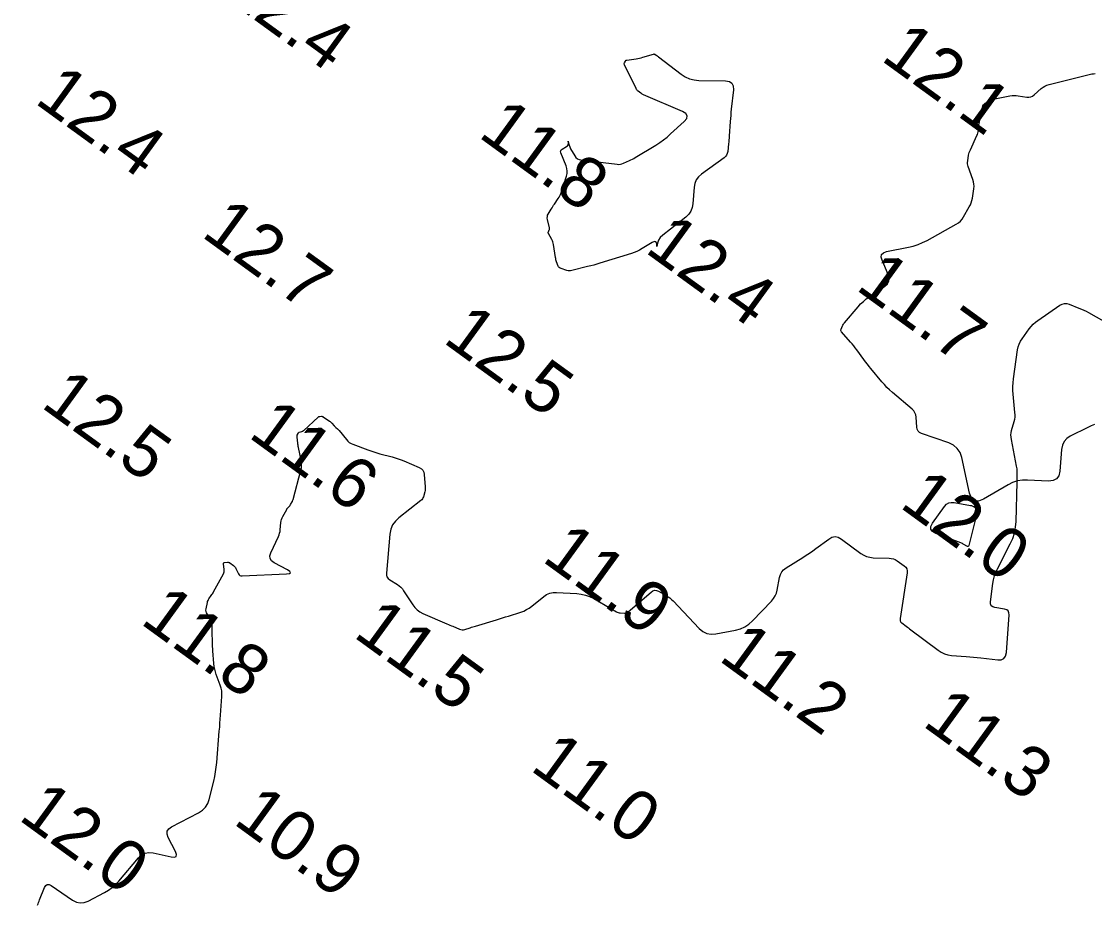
# Model space of a CAD drawing. Extents: x 815352 to 820877, y 582403 to 597439.
# Drawn here: x 818975.7 to 819081.8, y 587258.8 to 587346.1 of the extents above; entities that cross this region are included whole.
import ezdxf

# ---------------------------------------------------------------- set-up
doc = ezdxf.new("R2010")
doc.units = 0
doc.layers.add('V-CONT-EL12', color=7, linetype='Continuous')
doc.layers.add('V-TOPO-SOUN', color=7, linetype='Continuous')

msp = doc.modelspace()

# ---------------------------------------------------------------- linework, layer by layer
at = {"layer": 'V-CONT-EL12'}
for points in [[(819029.98, 587321.41), (819029.85, 587321.41), (819029.73, 587321.42), (819029.6, 587321.45), (819029.04, 587321.62), (819028.94, 587321.66), (819028.86, 587321.72), (819028.8, 587321.79), (819028.75, 587321.88), (819028.6, 587322.29), (819028.57, 587322.4), (819028.54, 587322.5), (819028.52, 587322.61), (819028.5, 587322.72), (819028.3, 587324.02), (819028.28, 587324.14), (819028.24, 587324.27), (819028.19, 587324.38), (819028.13, 587324.5), (819027.8, 587325.08), (819027.78, 587325.13), (819027.77, 587325.18), (819027.78, 587325.22), (819027.79, 587325.27), (819027.88, 587325.46), (819027.9, 587325.5), (819027.91, 587325.55), (819027.91, 587325.6), (819027.91, 587325.65), (819027.7, 587326.48), (819027.68, 587326.62), (819027.69, 587326.76), (819027.72, 587326.89), (819027.78, 587327.01), (819028.08, 587327.51), (819028.15, 587327.63), (819028.23, 587327.76), (819028.31, 587327.88), (819028.39, 587328), (819028.76, 587328.54), (819028.85, 587328.68), (819028.92, 587328.82), (819028.98, 587328.96), (819029.04, 587329.11), (819029.58, 587330.75), (819029.65, 587331.01), (819029.66, 587331.27), (819029.63, 587331.52), (819029.55, 587331.78), (819029.03, 587333.08), (819029, 587333.19), (819029.01, 587333.28), (819029.06, 587333.37), (819029.15, 587333.44), (819029.58, 587333.69), (819029.67, 587333.76), (819029.73, 587333.85), (819029.77, 587333.95), (819029.77, 587334.07), (819029.76, 587334.23), (819029.79, 587334.03), (819029.83, 587333.83), (819029.9, 587333.65), (819029.99, 587333.47), (819030.4, 587332.77), (819030.52, 587332.61), (819030.66, 587332.49), (819030.82, 587332.41), (819031.01, 587332.37), (819034.59, 587331.94), (819034.75, 587331.93), (819034.91, 587331.94), (819035.06, 587331.97), (819035.21, 587332.03), (819035.8, 587332.3), (819035.95, 587332.36), (819036.09, 587332.44), (819036.23, 587332.51), (819036.37, 587332.6), (819038.42, 587333.84), (819038.8, 587334.08), (819039.17, 587334.35), (819039.53, 587334.63), (819039.87, 587334.93), (819041.22, 587336.18), (819041.46, 587336.47), (819041.51, 587336.73), (819041.37, 587336.96), (819041.05, 587337.16), (819037.2, 587338.81), (819037.13, 587338.84), (819037.06, 587338.88), (819036.99, 587338.92), (819036.93, 587338.97), (819036.67, 587339.16), (819036.61, 587339.21), (819036.55, 587339.27), (819036.51, 587339.34), (819036.47, 587339.41), (819035.31, 587341.78), (819035.29, 587341.82), (819035.29, 587341.87), (819035.29, 587341.91), (819035.31, 587341.96), (819035.4, 587342.14), (819035.43, 587342.18), (819035.46, 587342.21), (819035.5, 587342.23), (819035.54, 587342.24), (819036.45, 587342.37), (819036.62, 587342.4), (819036.78, 587342.43), (819036.95, 587342.47), (819037.11, 587342.52), (819038.17, 587342.83), (819038.22, 587342.84), (819038.26, 587342.83), (819038.31, 587342.82), (819038.35, 587342.8), (819038.51, 587342.68), (819038.55, 587342.65), (819038.59, 587342.62), (819038.63, 587342.59), (819038.67, 587342.56), (819040.92, 587340.84), (819041.32, 587340.58), (819041.74, 587340.39), (819042.19, 587340.27), (819042.67, 587340.23), (819045.31, 587340.17), (819045.68, 587340.11), (819045.93, 587339.94), (819046.06, 587339.68), (819046.07, 587339.31), (819045.86, 587337.38), (819045.83, 587337.07), (819045.81, 587336.77), (819045.78, 587336.47), (819045.76, 587336.16), (819045.66, 587334.73), (819045.64, 587334.53), (819045.63, 587334.34), (819045.61, 587334.15), (819045.59, 587333.95), (819045.51, 587333.19), (819045.47, 587333), (819045.4, 587332.84), (819045.3, 587332.7), (819045.16, 587332.57), (819042.91, 587330.95), (819042.62, 587330.69), (819042.4, 587330.39), (819042.26, 587330.04), (819042.19, 587329.66), (819042.08, 587328.03), (819042.01, 587327.65), (819041.87, 587327.3), (819041.66, 587326.99), (819041.38, 587326.72), (819039.09, 587324.93), (819038.85, 587324.7), (819038.68, 587324.43), (819038.56, 587324.14), (819038.51, 587323.81), (819038.51, 587323.92), (819038.5, 587324.15), (819038.42, 587324.28), (819038.27, 587324.29), (819038.05, 587324.2), (819037.05, 587323.6), (819036.79, 587323.46), (819036.53, 587323.33), (819036.26, 587323.22), (819035.99, 587323.13), (819032.88, 587322.16), (819032.58, 587322.07), (819032.28, 587321.98), (819031.98, 587321.9), (819031.67, 587321.82), (819030.11, 587321.44)], [(819068.77, 587294.4), (819068.7, 587294.44), (819068.62, 587294.48), (819068.54, 587294.51), (819066.07, 587295.45), (819065.74, 587295.63), (819065.58, 587295.86), (819065.59, 587296.14), (819065.76, 587296.47), (819066.94, 587298.12), (819067.13, 587298.33), (819067.35, 587298.46), (819067.6, 587298.52), (819067.89, 587298.51), (819069.52, 587298.22), (819069.6, 587298.2), (819069.67, 587298.17), (819069.75, 587298.14), (819069.82, 587298.1), (819070.1, 587297.92), (819070.16, 587297.87), (819070.19, 587297.81), (819070.21, 587297.74), (819070.2, 587297.67), (819069.33, 587294.26), (819069.3, 587294.19), (819069.26, 587294.15), (819069.21, 587294.15), (819069.14, 587294.18), (819068.85, 587294.36)]]:
    msp.add_lwpolyline(points, close=True, dxfattribs=at)
for points in [[(819081.76, 587306.22), (819081.42, 587306.08), (819081.09, 587305.92), (819079.36, 587305.05), (819079.01, 587304.82), (819078.75, 587304.53), (819078.58, 587304.18), (819078.5, 587303.76), (819078.32, 587301.6), (819078.22, 587301.16), (819078.01, 587300.85), (819077.67, 587300.67), (819077.22, 587300.63), (819075.14, 587300.73), (819074.64, 587300.72), (819074.15, 587300.64), (819073.67, 587300.48), (819073.22, 587300.26), (819070.79, 587298.84), (819070.29, 587298.63), (819069.89, 587298.67), (819069.59, 587298.94), (819069.41, 587299.44), (819068.64, 587302.95), (819068.47, 587303.44), (819068.2, 587303.85), (819067.83, 587304.17), (819067.35, 587304.39), (819064.67, 587305.33), (819064.47, 587305.43), (819064.33, 587305.57), (819064.23, 587305.75), (819064.19, 587305.97), (819064.13, 587306.93), (819064.09, 587307.16), (819064.02, 587307.37), (819063.9, 587307.56), (819063.73, 587307.72), (819061.79, 587309.38), (819061.51, 587309.63), (819061.24, 587309.89), (819060.99, 587310.16), (819060.74, 587310.45), (819059.67, 587311.74), (819059.49, 587311.96), (819059.32, 587312.18), (819059.14, 587312.41), (819058.97, 587312.63), (819058.27, 587313.6), (819058.12, 587313.8), (819057.96, 587313.99), (819057.8, 587314.19), (819057.64, 587314.37), (819056.77, 587315.36), (819056.72, 587315.43), (819056.7, 587315.5), (819056.7, 587315.58), (819056.72, 587315.65), (819056.86, 587315.97), (819056.9, 587316.05), (819056.95, 587316.13), (819056.99, 587316.2), (819057.05, 587316.27), (819058.4, 587317.86), (819058.65, 587318.13), (819058.92, 587318.39), (819059.21, 587318.63), (819059.51, 587318.85), (819061.05, 587319.9), (819061.3, 587320.13), (819061.45, 587320.4), (819061.47, 587320.7), (819061.37, 587321.03), (819060.76, 587322.45), (819060.68, 587322.76), (819060.72, 587323.01), (819060.9, 587323.19), (819061.21, 587323.3), (819063.37, 587323.73), (819063.85, 587323.85), (819064.32, 587324), (819064.77, 587324.19), (819065.21, 587324.41), (819068.09, 587326.01), (819068.31, 587326.15), (819068.51, 587326.32), (819068.68, 587326.52), (819068.82, 587326.73), (819069.38, 587327.72), (819069.49, 587327.93), (819069.58, 587328.14), (819069.64, 587328.37), (819069.69, 587328.59), (819069.84, 587329.52), (819069.86, 587329.76), (819069.85, 587329.98), (819069.81, 587330.21), (819069.75, 587330.43), (819069.28, 587331.71), (819069.24, 587331.85), (819069.22, 587331.98), (819069.22, 587332.12), (819069.23, 587332.26), (819069.32, 587332.83), (819069.35, 587332.97), (819069.38, 587333.1), (819069.43, 587333.24), (819069.49, 587333.37), (819070.14, 587334.78), (819070.19, 587334.89), (819070.23, 587335.02), (819070.26, 587335.14), (819070.28, 587335.27), (819070.34, 587335.88), (819070.35, 587335.96), (819070.37, 587336.04), (819070.38, 587336.12), (819070.4, 587336.19), (819070.49, 587336.5), (819070.51, 587336.58), (819070.53, 587336.66), (819070.55, 587336.73), (819070.56, 587336.81), (819070.69, 587337.58), (819070.72, 587337.7), (819070.78, 587337.8), (819070.86, 587337.89), (819070.96, 587337.96), (819071.42, 587338.22), (819071.54, 587338.28), (819071.66, 587338.32), (819071.78, 587338.36), (819071.91, 587338.39), (819073.4, 587338.69), (819073.61, 587338.72), (819073.82, 587338.73), (819074.02, 587338.73), (819074.23, 587338.71), (819075.07, 587338.57), (819075.27, 587338.56), (819075.46, 587338.6), (819075.64, 587338.67), (819075.8, 587338.79), (819076.49, 587339.42), (819076.67, 587339.56), (819076.86, 587339.67), (819077.06, 587339.76), (819077.27, 587339.83), (819081.48, 587340.86), (819081.65, 587340.89), (819081.82, 587340.91)], [(818977.3, 587258.72), (818977.36, 587258.84), (818977.41, 587258.97), (818977.47, 587259.1), (818977.52, 587259.23), (818978.01, 587260.45), (818978.13, 587260.65), (818978.27, 587260.75), (818978.45, 587260.75), (818978.65, 587260.65), (818980.77, 587259.21), (818981.15, 587259.01), (818981.53, 587258.93), (818981.93, 587258.97), (818982.32, 587259.12), (818983.94, 587259.97), (818984.32, 587260.2), (818984.69, 587260.46), (818985.02, 587260.75), (818985.33, 587261.08), (818987.29, 587263.4), (818987.59, 587263.68), (818987.93, 587263.85), (818988.31, 587263.92), (818988.72, 587263.88), (818990.53, 587263.48), (818990.85, 587263.45), (818991.02, 587263.53), (818991.05, 587263.71), (818990.94, 587264.01), (818990.22, 587265.4), (818990.11, 587265.73), (818990.12, 587266.02), (818990.27, 587266.26), (818990.56, 587266.46), (818993.23, 587267.84), (818993.61, 587268.09), (818993.91, 587268.39), (818994.13, 587268.75), (818994.28, 587269.17), (818994.72, 587270.98), (818994.82, 587271.43), (818994.9, 587271.89), (818994.97, 587272.34), (818995.02, 587272.81), (818995.27, 587275.9), (818995.31, 587276.3), (818995.34, 587276.7), (818995.37, 587277.1), (818995.4, 587277.5), (818995.53, 587279.34), (818995.53, 587279.63), (818995.51, 587279.9), (818995.46, 587280.17), (818995.37, 587280.44), (818994.97, 587281.51), (818994.89, 587281.78), (818994.82, 587282.04), (818994.77, 587282.31), (818994.73, 587282.59), (818994.63, 587283.85), (818994.62, 587284.05), (818994.61, 587284.26), (818994.6, 587284.46), (818994.59, 587284.67), (818994.56, 587285.71), (818994.56, 587285.8), (818994.56, 587285.9), (818994.56, 587285.99), (818994.56, 587286.09), (818994.58, 587286.47), (818994.57, 587286.56), (818994.55, 587286.65), (818994.52, 587286.73), (818994.48, 587286.82), (818994.06, 587287.49), (818994, 587287.61), (818993.96, 587287.74), (818993.95, 587287.87), (818993.97, 587288.01), (818994.1, 587288.64), (818994.12, 587288.73), (818994.16, 587288.83), (818994.2, 587288.91), (818994.25, 587289), (818994.48, 587289.33), (818994.54, 587289.41), (818994.6, 587289.49), (818994.65, 587289.58), (818994.7, 587289.67), (818995.68, 587291.46), (818995.72, 587291.57), (818995.75, 587291.67), (818995.76, 587291.78), (818995.76, 587291.89), (818995.69, 587292.44), (818995.69, 587292.5), (818995.71, 587292.54), (818995.75, 587292.57), (818995.8, 587292.58), (818996.08, 587292.6), (818996.14, 587292.6), (818996.21, 587292.59), (818996.27, 587292.57), (818996.32, 587292.53), (818996.68, 587292.28), (818996.75, 587292.22), (818996.81, 587292.16), (818996.87, 587292.08), (818996.91, 587292), (818997.16, 587291.47), (818997.23, 587291.37), (818997.31, 587291.3), (818997.41, 587291.26), (818997.53, 587291.25), (819001.91, 587291.46), (819002.2, 587291.49), (819002.3, 587291.57), (819002.24, 587291.68), (819002, 587291.84), (819000.68, 587292.55), (819000.43, 587292.74), (819000.29, 587292.97), (819000.27, 587293.23), (819000.36, 587293.53), (819001.11, 587295.15), (819001.18, 587295.31), (819001.23, 587295.47), (819001.27, 587295.64), (819001.29, 587295.81), (819001.36, 587296.54), (819001.38, 587296.69), (819001.42, 587296.84), (819001.47, 587296.98), (819001.54, 587297.11), (819001.94, 587297.83), (819001.96, 587297.87), (819001.99, 587297.91), (819002.02, 587297.95), (819002.06, 587297.99), (819002.2, 587298.14), (819002.23, 587298.18), (819002.26, 587298.22), (819002.29, 587298.26), (819002.32, 587298.3), (819002.46, 587298.56), (819002.49, 587298.61), (819002.52, 587298.67), (819002.54, 587298.73), (819002.56, 587298.8), (819003.34, 587301.7), (819003.39, 587301.95), (819003.41, 587302.19), (819003.4, 587302.44), (819003.36, 587302.68), (819003.09, 587303.94), (819003.07, 587304.05), (819003.05, 587304.16), (819003.03, 587304.27), (819003.02, 587304.38), (819002.96, 587304.95), (819002.96, 587305), (819002.96, 587305.05), (819002.97, 587305.1), (819002.98, 587305.15), (819003.05, 587305.33), (819003.07, 587305.38), (819003.1, 587305.41), (819003.14, 587305.44), (819003.18, 587305.46), (819003.43, 587305.53), (819003.49, 587305.55), (819003.54, 587305.57), (819003.59, 587305.61), (819003.63, 587305.64), (819005.04, 587306.95), (819005.07, 587306.98), (819005.11, 587307), (819005.15, 587307.01), (819005.19, 587307.02), (819005.37, 587307.03), (819005.41, 587307.03), (819005.45, 587307.02), (819005.49, 587307.01), (819005.53, 587306.99), (819006.16, 587306.56), (819006.23, 587306.51), (819006.28, 587306.46), (819006.34, 587306.41), (819006.39, 587306.35), (819006.62, 587306.1), (819006.65, 587306.05), (819006.7, 587306.01), (819006.74, 587305.97), (819006.78, 587305.93), (819006.96, 587305.78), (819007, 587305.74), (819007.04, 587305.7), (819007.08, 587305.65), (819007.12, 587305.61), (819007.83, 587304.73), (819007.96, 587304.58), (819008.12, 587304.45), (819008.29, 587304.34), (819008.48, 587304.26), (819009.95, 587303.7), (819010.24, 587303.6), (819010.54, 587303.5), (819010.84, 587303.41), (819011.14, 587303.32), (819012.35, 587303.01), (819012.65, 587302.92), (819012.94, 587302.83), (819013.24, 587302.72), (819013.52, 587302.61), (819015.03, 587301.97), (819015.24, 587301.85), (819015.39, 587301.7), (819015.48, 587301.51), (819015.53, 587301.28), (819015.62, 587300.05), (819015.63, 587299.92), (819015.62, 587299.8), (819015.6, 587299.68), (819015.57, 587299.56), (819015.45, 587299.08), (819015.4, 587298.97), (819015.35, 587298.86), (819015.27, 587298.77), (819015.18, 587298.69), (819013.02, 587296.99), (819012.67, 587296.66), (819012.4, 587296.29), (819012.23, 587295.86), (819012.14, 587295.39), (819011.78, 587291.54), (819011.79, 587291.33), (819011.84, 587291.15), (819011.95, 587291), (819012.12, 587290.87), (819012.87, 587290.4), (819013.05, 587290.27), (819013.22, 587290.13), (819013.36, 587289.97), (819013.49, 587289.79), (819014.38, 587288.41), (819014.59, 587288.13), (819014.83, 587287.9), (819015.1, 587287.7), (819015.4, 587287.54), (819017.76, 587286.53), (819017.91, 587286.46), (819018.06, 587286.4), (819018.21, 587286.33), (819018.36, 587286.27), (819019.01, 587285.99), (819019.14, 587285.95), (819019.27, 587285.93), (819019.4, 587285.94), (819019.53, 587285.97), (819020.06, 587286.13), (819020.19, 587286.18), (819020.33, 587286.22), (819020.46, 587286.26), (819020.59, 587286.3), (819022.66, 587286.92), (819022.96, 587287.01), (819023.26, 587287.1), (819023.56, 587287.2), (819023.86, 587287.29), (819025.06, 587287.67), (819025.36, 587287.78), (819025.64, 587287.92), (819025.9, 587288.08), (819026.16, 587288.26), (819027.33, 587289.21), (819027.61, 587289.4), (819027.92, 587289.54), (819028.25, 587289.61), (819028.59, 587289.62), (819030.59, 587289.51), (819031.03, 587289.46), (819031.46, 587289.36), (819031.87, 587289.21), (819032.27, 587289.01), (819034.51, 587287.71), (819034.6, 587287.67), (819034.7, 587287.63), (819034.79, 587287.61), (819034.89, 587287.6), (819035.3, 587287.57), (819035.4, 587287.58), (819035.5, 587287.6), (819035.58, 587287.64), (819035.67, 587287.69), (819037.95, 587289.66), (819038.12, 587289.78), (819038.29, 587289.83), (819038.48, 587289.81), (819038.66, 587289.74), (819039.43, 587289.31), (819039.62, 587289.2), (819039.8, 587289.07), (819039.97, 587288.93), (819040.12, 587288.78), (819042.69, 587286.05), (819043.05, 587285.75), (819043.44, 587285.56), (819043.88, 587285.48), (819044.34, 587285.52), (819046.29, 587285.89), (819046.76, 587286.02), (819047.2, 587286.21), (819047.6, 587286.47), (819047.96, 587286.8), (819049.85, 587288.77), (819050.05, 587289.01), (819050.21, 587289.27), (819050.33, 587289.55), (819050.4, 587289.85), (819050.63, 587291.1), (819050.72, 587291.39), (819050.86, 587291.65), (819051.04, 587291.87), (819051.29, 587292.06), (819052.93, 587293.08), (819053.26, 587293.29), (819053.59, 587293.51), (819053.91, 587293.74), (819054.23, 587293.97), (819055.5, 587294.9), (819055.81, 587295.08), (819056.13, 587295.14), (819056.44, 587295.08), (819056.76, 587294.9), (819058.67, 587293.47), (819058.95, 587293.3), (819059.24, 587293.17), (819059.55, 587293.09), (819059.88, 587293.05), (819061.46, 587293.01), (819061.68, 587292.99), (819061.88, 587292.94), (819062.07, 587292.86), (819062.25, 587292.75), (819062.96, 587292.24), (819063.12, 587292.11), (819063.21, 587291.95), (819063.26, 587291.76), (819063.25, 587291.56), (819062.54, 587287.04), (819062.54, 587286.91), (819062.57, 587286.8), (819062.63, 587286.69), (819062.72, 587286.6), (819063.16, 587286.27), (819063.27, 587286.19), (819063.38, 587286.11), (819063.49, 587286.03), (819063.6, 587285.94), (819066.31, 587283.9), (819066.61, 587283.7), (819066.93, 587283.56), (819067.26, 587283.46), (819067.62, 587283.4), (819069.08, 587283.29), (819069.44, 587283.26), (819069.81, 587283.22), (819070.17, 587283.19), (819070.54, 587283.15), (819072.2, 587282.96), (819072.55, 587282.97), (819072.81, 587283.09), (819072.97, 587283.32), (819073.05, 587283.67), (819073.32, 587287.4), (819073.3, 587287.62), (819073.22, 587287.79), (819073.08, 587287.9), (819072.87, 587287.97), (819071.9, 587288.13), (819071.7, 587288.2), (819071.56, 587288.31), (819071.48, 587288.48), (819071.48, 587288.7), (819071.71, 587290.51), (819071.78, 587290.88), (819071.87, 587291.25), (819072, 587291.61), (819072.16, 587291.95), (819073.44, 587294.41), (819073.68, 587294.94), (819073.85, 587295.49), (819073.96, 587296.06), (819074.01, 587296.64), (819074.1, 587300.52), (819074.11, 587300.65), (819074.11, 587300.78), (819074.11, 587300.91), (819074.11, 587301.04), (819074.11, 587301.57), (819074.11, 587301.7), (819074.1, 587301.83), (819074.08, 587301.96), (819074.06, 587302.09), (819073.54, 587304.73), (819073.51, 587304.95), (819073.5, 587305.18), (819073.53, 587305.4), (819073.57, 587305.62), (819073.82, 587306.51), (819073.88, 587306.73), (819073.91, 587306.95), (819073.92, 587307.18), (819073.9, 587307.41), (819073.72, 587309.21), (819073.7, 587309.59), (819073.69, 587309.97), (819073.71, 587310.35), (819073.75, 587310.72), (819074.16, 587313.6), (819074.22, 587313.89), (819074.31, 587314.17), (819074.44, 587314.44), (819074.6, 587314.69), (819075.31, 587315.68), (819075.5, 587315.91), (819075.71, 587316.13), (819075.93, 587316.33), (819076.17, 587316.51), (819078.34, 587318.01), (819078.56, 587318.12), (819078.78, 587318.18), (819079.01, 587318.17), (819079.25, 587318.11), (819080.22, 587317.73), (819080.46, 587317.63), (819080.69, 587317.52), (819080.92, 587317.41), (819081.15, 587317.29), (819084.43, 587315.44)]]:
    msp.add_lwpolyline(points, dxfattribs=at)

# ---------------------------------------------------------------- texts
at = {"layer": 'V-TOPO-SOUN'}
for s, p in [('12.4 ', (818995.45, 587348.6)), ('12.1 ', (819060.53, 587342.29)), ('12.4 ', (818976.91, 587338.06)), ('11.8 ', (819020.75, 587334.72)), ('12.7 ', (818993.38, 587324.88)), ('12.4 ', (819037.21, 587323.33)), ('11.7 ', (819058.05, 587319.63)), ('12.5 ', (819017.26, 587314.41)), ('12.5 ', (818977.53, 587308.01)), ('11.6 ', (818998.02, 587305.05)), ('12.0 ', (819062.38, 587298.12)), ('11.9 ', (819027.04, 587292.79)), ('11.8 ', (818987.35, 587286.62)), ('11.5 ', (819008.4, 587285.31)), ('11.2 ', (819044.5, 587282.98)), ('11.3 ', (819064.64, 587276.52)), ('11.0 ', (819025.87, 587272.13)), ('12.0 ', (818975.31, 587267.24)), ('10.9 ', (818996.53, 587266.84))]:
    msp.add_text(s, height=5, rotation=324, dxfattribs=at).set_placement(p)

doc.saveas('drawing.dxf')
